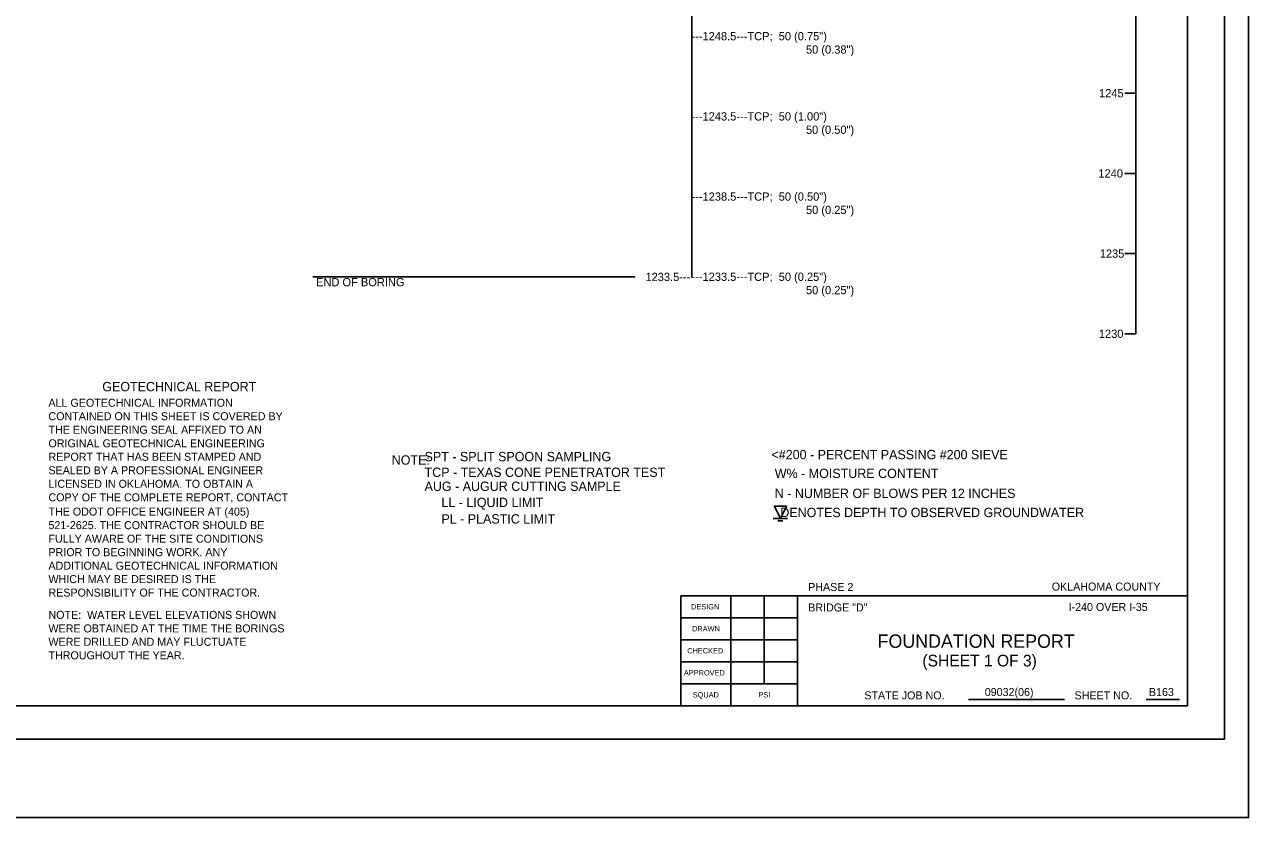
# Model space of a CAD drawing. Extents: x -93 to 177, y 25 to 84.
# Drawn here: x -75.69 to -57.33, y 25.37 to 37.26 of the extents above; entities that cross this region are included whole.
import ezdxf

# ---------------------------------------------------------------- set-up
doc = ezdxf.new("R2010")
doc.units = 0
for name, color, linetype in [('SHT_Plot_Shape_Full', 7, 'Continuous'), ('SHT_Plot_Shape_Half', 7, 'Continuous'), ('SHT_Sheet_Border', 7, 'Continuous'), ('SHT_Standard_Sheet_Lines', 7, 'Continuous'), ('SHT_Standard_Sheet_Txt', 7, 'Continuous'), ('T-Subtitle', 7, 'Continuous'), ('T-Title', 7, 'Continuous'), ('Text', 7, 'Continuous')]:
    doc.layers.add(name, color=color, linetype=linetype)

# ---------------------------------------------------------------- blocks, each defined once
blk = doc.blocks.new('DGRFC_WTLEV1')
for points in [[(-0.0127, 0), (0.0127, 0)], [(0, 0), (0.0106, 0.0212), (-0.0106, 0.0212), (0, 0)], [(-0.0042, -0.0042), (0.0042, -0.0042)]]:
    blk.add_lwpolyline(points)

msp = doc.modelspace()

# ---------------------------------------------------------------- linework, layer by layer
msp.add_line((-59.02, 32.62), (-59.02, 44.639))
for points in [[(-65.682, 44.557), (-65.682, 33.466)], [(-59.02, 36.226), (-59.186, 36.226)], [(-59.02, 35.024), (-59.186, 35.024)], [(-59.02, 33.822), (-59.186, 33.822)], [(-71.362, 33.472), (-66.53, 33.472)], [(-59.02, 32.62), (-59.186, 32.62)], [(-59.02, 32.62), (-59.186, 32.62)]]:
    msp.add_lwpolyline(points)
at = {"layer": 'SHT_Plot_Shape_Full'}
msp.add_lwpolyline([(-93.331, 49.368), (-57.331, 49.368), (-57.331, 25.368), (-93.331, 25.368)], close=True, dxfattribs=at)
at = {"layer": 'SHT_Plot_Shape_Half'}
msp.add_lwpolyline([(-91.694, 48.543), (-57.694, 48.543), (-57.694, 26.543), (-91.694, 26.543)], close=True, dxfattribs=at)
at = {"layer": 'SHT_Sheet_Border'}
for p, q in [((-65.844, 27.043), (-65.844, 28.693)), ((-65.844, 28.693), (-58.244, 28.693)), ((-64.094, 27.043), (-64.094, 28.694))]:
    msp.add_line(p, q, dxfattribs=at)
msp.add_lwpolyline([(-58.244, 27.043), (-89.744, 27.043), (-89.744, 48.043), (-58.244, 48.043)], close=True, dxfattribs=at)
at = {"layer": 'SHT_Standard_Sheet_Lines'}
for p, q in [((-65.094, 27.043), (-65.094, 28.694)), ((-64.594, 27.373), (-64.594, 28.694)), ((-61.533, 27.139), (-60.093, 27.139)), ((-58.868, 27.139), (-58.366, 27.139))]:
    msp.add_line(p, q, dxfattribs=at)
for points in [[(-64.094, 28.363), (-65.844, 28.363)], [(-64.094, 28.033), (-65.844, 28.033)], [(-64.094, 27.703), (-65.844, 27.703)], [(-64.094, 27.373), (-65.844, 27.373)]]:
    msp.add_lwpolyline(points, dxfattribs=at)

# ---------------------------------------------------------------- block references
at = {"xscale": 8.503919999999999, "yscale": 8.503919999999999}
msp.add_blockref('DGRFC_WTLEV1', (-64.352, 29.853), dxfattribs=at)

# ---------------------------------------------------------------- texts
for s, p in [('---1248.5---TCP;  50 (0.75")', (-65.685, 37.019)), ('50 (0.38")', (-63.968, 36.819)), ('1245', (-59.573, 36.164)), ('---1243.5---TCP;  50 (1.00")', (-65.685, 35.817)), ('50 (0.50")', (-63.968, 35.617)), ('1240', (-59.583, 34.962)), ('---1238.5---TCP;  50 (0.50")', (-65.685, 34.615)), ('50 (0.25")', (-63.968, 34.415)), ('1235', (-59.562, 33.76)), ('END OF BORING', (-71.315, 33.332)), ('1233.5---', (-66.375, 33.41)), ('---1233.5---TCP;  50 (0.25")', (-65.685, 33.413)), ('50 (0.25")', (-63.968, 33.213)), ('1230', (-59.576, 32.558))]:
    msp.add_text(s, height=0.124).set_placement(p)
at = {"layer": 'SHT_Standard_Sheet_Txt'}
for s, height, p in [('PHASE 2', 0.12, (-63.935, 28.764)), ('OKLAHOMA COUNTY', 0.12, (-60.282, 28.77)), ('DESIGN', 0.08, (-65.691, 28.488)), ('BRIDGE "D" ', 0.12, (-63.935, 28.457)), ('I-240 OVER I-35', 0.12, (-60.03, 28.464)), ('DRAWN', 0.08, (-65.677, 28.158)), ('CHECKED', 0.08, (-65.749, 27.828)), ('APPROVED', 0.08, (-65.799, 27.498)), ('SQUAD', 0.08, (-65.667, 27.168)), ('PSI', 0.08, (-64.681, 27.168)), ('STATE JOB NO.', 0.12, (-63.093, 27.139)), ('09032(06)', 0.12, (-61.287, 27.189)), ('SHEET NO. ', 0.12, (-59.94, 27.139)), ('B163', 0.12, (-58.825, 27.189))]:
    msp.add_text(s, height=height, dxfattribs=at).set_placement(p)
at = {"layer": 'T-Subtitle'}
msp.add_text('(SHEET 1 OF 3)', height=0.175, dxfattribs=at).set_placement((-62.222, 27.633))
at = {"layer": 'T-Title'}
msp.add_text('FOUNDATION REPORT', height=0.2, dxfattribs=at).set_placement((-62.894, 27.912))
at = {"layer": 'Text'}
for s, height, p in [('GEOTECHNICAL REPORT', 0.14, (-74.521, 31.758)), ('ALL GEOTECHNICAL INFORMATION ', 0.12, (-75.328, 31.526)), ('CONTAINED ON THIS SHEET IS COVERED BY ', 0.12, (-75.328, 31.324)), ('THE ENGINEERING SEAL AFFIXED TO AN ', 0.12, (-75.328, 31.121)), ('ORIGINAL GEOTECHNICAL ENGINEERING ', 0.12, (-75.328, 30.918)), ('    SPT - SPLIT SPOON SAMPLING', 0.14, (-69.896, 30.709)), (' <#200 - PERCENT PASSING #200 SIEVE', 0.14, (-64.537, 30.739)), ('REPORT THAT HAS BEEN STAMPED AND ', 0.12, (-75.328, 30.716)), ('NOTE:', 0.14, (-70.18, 30.658)), ('SEALED BY A PROFESSIONAL ENGINEER ', 0.12, (-75.328, 30.513)), ('    TCP - TEXAS CONE PENETRATOR TEST', 0.14, (-69.896, 30.474)), ('W% - MOISTURE CONTENT', 0.14, (-64.436, 30.457)), ('LICENSED IN OKLAHOMA. TO OBTAIN A ', 0.12, (-75.328, 30.311)), ('    AUG - AUGUR CUTTING SAMPLE', 0.14, (-69.896, 30.264)), ('N - NUMBER OF BLOWS PER 12 INCHES', 0.14, (-64.436, 30.158)), ('COPY OF THE COMPLETE REPORT, CONTACT ', 0.12, (-75.328, 30.108)), (' LL - LIQUID LIMIT', 0.14, (-69.487, 30.022)), ('THE ODOT OFFICE ENGINEER AT (405) ', 0.12, (-75.328, 29.894)), ('    DENOTES DEPTH TO OBSERVED GROUNDWATER', 0.14, (-64.561, 29.871)), ('521-2625. THE CONTRACTOR SHOULD BE ', 0.12, (-75.328, 29.691)), (' PL - PLASTIC LIMIT', 0.14, (-69.487, 29.775)), ('FULLY AWARE OF THE SITE CONDITIONS ', 0.12, (-75.328, 29.488)), ('PRIOR TO BEGINNING WORK. ANY ', 0.12, (-75.328, 29.286)), ('ADDITIONAL GEOTECHNICAL INFORMATION ', 0.12, (-75.328, 29.083)), ('WHICH MAY BE DESIRED IS THE ', 0.12, (-75.328, 28.882)), ('RESPONSIBILITY OF THE CONTRACTOR.', 0.12, (-75.328, 28.68)), ('NOTE:  WATER LEVEL ELEVATIONS SHOWN ', 0.12, (-75.328, 28.346)), ('WERE OBTAINED AT THE TIME THE BORINGS ', 0.12, (-75.328, 28.143)), ('WERE DRILLED AND MAY FLUCTUATE ', 0.12, (-75.328, 27.942)), ('THROUGHOUT THE YEAR.', 0.12, (-75.328, 27.74))]:
    msp.add_text(s, height=height, dxfattribs=at).set_placement(p)

doc.saveas('drawing.dxf')
